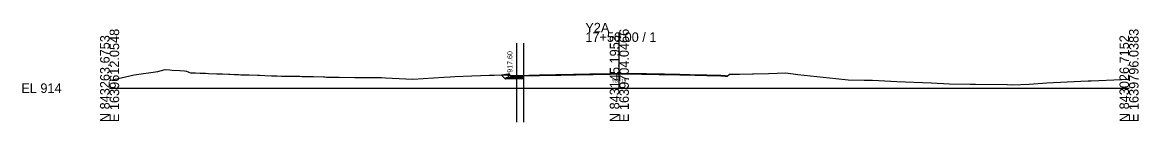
# Model space of a CAD drawing. Extents: x -26 to 303, y -10 to 10517.
# Drawn here: x -25.7 to 302.8, y 6989.9 to 7019.3 of the extents above; entities that cross this region are included whole.
import ezdxf

# ---------------------------------------------------------------- set-up
doc = ezdxf.new("R2010")
doc.units = 0
for name, color, linetype in [('Exist Cross Section Cell', 7, 'Continuous'), ('Exist XS Center Line Elevation Label', 7, 'Continuous'), ('Exist XS Ground Line', 7, 'Continuous'), ('Prop CMT Conc Surface', 7, 'Continuous'), ('Prop CMT Concrete Structures', 7, 'Continuous'), ('Prop CMT Pvmt Course 1', 7, 'Continuous'), ('Prop CMT Pvmt Course 1 CG', 7, 'Continuous'), ('Prop CMT Pvmt Course 2', 7, 'Continuous'), ('Prop CMT Pvmt Surface Overlay', 7, 'Continuous'), ('Prop CMT Slope Grass', 7, 'Continuous'), ('Prop CMT Subgrade Earthwork', 7, 'Continuous'), ('Prop XS Hydro Elevations', 7, 'Continuous'), ('Scratch_Level_0', 7, 'Continuous'), ('Scratch_Level_2', 7, 'Continuous')]:
    doc.layers.add(name, color=color, linetype=linetype)

msp = doc.modelspace()

# ---------------------------------------------------------------- linework, layer by layer
at = {"layer": 'Exist Cross Section Cell'}
for p, q in [((150, 7000), (150, 7016.43)), ((0, 7000), (150, 7000)), ((150, 7000), (300, 7000))]:
    msp.add_line(p, q, dxfattribs=at)
at = {"layer": 'Exist XS Ground Line'}
msp.add_lwpolyline([(0, 7002.24), (7.25, 7003.95), (14.19, 7004.92), (16.35, 7005.48), (17.74, 7005.39), (18.43, 7005.34), (20.7, 7005.16), (22.08, 7005.06), (22.61, 7005.02), (23.34, 7004.71), (23.76, 7004.53), (24.1, 7004.52), (25.23, 7004.51), (26.63, 7004.46), (27.63, 7004.41), (28.23, 7004.38), (29.07, 7004.34), (31.56, 7004.25), (33.23, 7004.18), (35.01, 7004.11), (35.38, 7004.1), (36.79, 7004.05), (37.89, 7004), (38.57, 7003.97), (39.45, 7003.94), (40.35, 7003.91), (41.05, 7003.89), (43.53, 7003.8), (44.22, 7003.78), (45.7, 7003.73), (47.61, 7003.67), (49.26, 7003.61), (50.55, 7003.55), (51.15, 7003.53), (52.55, 7003.53), (53.28, 7003.54), (53.75, 7003.53), (55.97, 7003.5), (56.53, 7003.48), (56.88, 7003.48), (58.17, 7003.44), (60.04, 7003.41), (62.94, 7003.31), (63.37, 7003.3), (63.8, 7003.28), (65.58, 7003.23), (67.53, 7003.19), (72.18, 7003.16), (74.02, 7003.13), (75.17, 7003.12), (75.67, 7003.11), (76.35, 7003.1), (80.01, 7003.09), (81.19, 7003.04), (87.18, 7002.74), (89.21, 7002.69), (98.34, 7003.28), (100.19, 7003.33), (101.57, 7003.39), (106.55, 7003.65), (111.66, 7003.81), (113.16, 7003.83), (117.53, 7003.89), (118.11, 7003.44), (118.57, 7003.46), (119.76, 7003.5), (120.25, 7003.57), (120.98, 7003.62), (123.34, 7003.68), (124.09, 7003.7), (125.06, 7003.72), (125.87, 7003.74), (126.51, 7003.76), (127.66, 7003.78), (129.13, 7003.82), (129.67, 7003.83), (131.36, 7003.86), (132.8, 7003.87), (133.21, 7003.88), (134.78, 7003.92), (136, 7003.94), (136.56, 7003.95), (137.29, 7003.97), (138.35, 7004), (139.17, 7004.01), (141.36, 7004.05), (142.33, 7004.07), (143.26, 7004.08), (145.5, 7004.11), (147.26, 7004.14), (148.66, 7004.17), (149.52, 7004.19), (150, 7004.19), (151.83, 7004.2), (152.6, 7004.2), (153.59, 7004.19), (154.99, 7004.18), (156.65, 7004.16), (157.41, 7004.15), (157.85, 7004.14), (158.16, 7004.14), (159.73, 7004.09), (161.75, 7004.07), (163.29, 7004.05), (164.49, 7004.01), (165.82, 7003.99), (167.78, 7003.96), (168.61, 7003.94), (169.84, 7003.91), (170.82, 7003.88), (172.2, 7003.84), (173.99, 7003.81), (175.76, 7003.75), (177.15, 7003.73), (177.54, 7003.72), (178.05, 7003.71), (179.84, 7003.66), (181.16, 7003.56), (181.78, 7003.52), (182.46, 7004.08), (182.96, 7004.09), (185.33, 7004.1), (189.18, 7004.2), (189.52, 7004.21), (193.9, 7004.33), (198.96, 7004.47), (202.52, 7004.07), (213.7, 7002.8), (217.37, 7002.49), (222.1, 7002.4), (224.5, 7002.37), (226.36, 7002.22), (231.62, 7001.99), (241.81, 7001.59), (247.21, 7001.32), (253.28, 7001.21), (254.11, 7001.19), (254.8, 7001.21), (264.25, 7001.04), (265.63, 7001.02), (270.66, 7001.19), (275.81, 7001.6), (285.83, 7002.04), (287.93, 7002.11), (288.89, 7002.14), (297.79, 7002.55), (300, 7002.65)], dxfattribs=at)
at = {"layer": 'Prop CMT Conc Surface'}
msp.add_lwpolyline([(117.78, 7003.6), (117.78, 7004.1), (117.28, 7004.1)], dxfattribs=at)
at = {"layer": 'Prop CMT Concrete Structures'}
for points in [[(119.78, 7003.72), (117.78, 7003.6), (117.78, 7004.1), (117.28, 7004.1)], [(117.28, 7004.1), (117.28, 7003.09), (119.78, 7003.14)]]:
    msp.add_lwpolyline(points, dxfattribs=at)
at = {"layer": 'Prop CMT Pvmt Course 1'}
for p, q in [((119.78, 7003.72), (121.78, 7003.76)), ((119.78, 7003.72), (119.78, 7003.47)), ((119.78, 7003.47), (121.78, 7003.51)), ((121.78, 7003.76), (121.78, 7003.51))]:
    msp.add_line(p, q, dxfattribs=at)
at = {"layer": 'Prop CMT Pvmt Course 1 CG'}
for p, q in [((119.78, 7003.14), (119.78, 7002.81)), ((119.78, 7002.81), (121.78, 7002.85)), ((121.78, 7003.18), (121.78, 7002.85))]:
    msp.add_line(p, q, dxfattribs=at)
for points in [[(119.78, 7003.14), (116.78, 7003.08), (116.44, 7002.74)], [(116.48, 7002.75), (119.78, 7002.81)]]:
    msp.add_lwpolyline(points, dxfattribs=at)
at = {"layer": 'Prop CMT Pvmt Course 2'}
for p, q in [((119.78, 7003.14), (119.78, 7003.47)), ((119.78, 7003.14), (121.78, 7003.18)), ((121.78, 7003.18), (121.78, 7003.51))]:
    msp.add_line(p, q, dxfattribs=at)
at = {"layer": 'Prop CMT Pvmt Surface Overlay'}
msp.add_lwpolyline([(121.78, 7003.76), (123.34, 7003.8), (124.09, 7003.82), (125.05, 7003.85), (126.51, 7003.88), (127.65, 7003.9), (129.13, 7003.94), (129.67, 7003.95), (131.36, 7003.98), (132.8, 7004), (133.21, 7004.01), (134.78, 7004.05), (136, 7004.06), (136.56, 7004.08), (137.28, 7004.1), (138.34, 7004.12), (139.17, 7004.14), (141.36, 7004.17), (142.33, 7004.2), (143.25, 7004.21), (145.5, 7004.23), (147.25, 7004.27), (148.66, 7004.3), (149.51, 7004.31), (151.83, 7004.33), (152.6, 7004.33), (153.59, 7004.32), (155, 7004.31), (156.65, 7004.29), (157.41, 7004.27), (157.85, 7004.27), (158.16, 7004.26), (159.73, 7004.22), (161.75, 7004.2), (163.29, 7004.17), (164.49, 7004.13), (165.82, 7004.11), (167.79, 7004.09), (168.61, 7004.06), (169.84, 7004.03), (170.82, 7004), (172.2, 7003.97), (173.99, 7003.94), (175.77, 7003.88), (177.15, 7003.85), (177.55, 7003.85), (178.05, 7003.84), (179.84, 7003.78), (181.17, 7003.69), (181.92, 7003.63)], dxfattribs=at)
at = {"layer": 'Prop CMT Slope Grass'}
msp.add_lwpolyline([(117.28, 7004.1), (115.33, 7003.86)], dxfattribs=at)
at = {"layer": 'Prop CMT Subgrade Earthwork'}
msp.add_lwpolyline([(119.78, 7002.81), (116.44, 7002.74), (115.33, 7003.86)], dxfattribs=at)
at = {"layer": 'Scratch_Level_0'}
for p, q in [((119.78, 7013.29), (119.78, 6989.94)), ((121.78, 7013.29), (121.78, 6989.94))]:
    msp.add_line(p, q, dxfattribs=at)
at = {"layer": 'Scratch_Level_2'}
msp.add_line((121.78, 7003.64), (120.98, 7003.62), dxfattribs=at)
for points in [[(120.98, 7003.62), (120.25, 7003.57), (119.76, 7003.5), (118.57, 7003.46), (118.11, 7003.44), (117.53, 7003.89), (115.33, 7003.86)], [(115.33, 7003.86), (116.44, 7002.74), (119.78, 7002.81), (121.78, 7002.85), (121.78, 7003.64)], [(115.33, 7003.86), (116.44, 7002.74), (119.78, 7002.81), (121.78, 7002.85), (121.78, 7003.64)]]:
    msp.add_lwpolyline(points, dxfattribs=at)

# ---------------------------------------------------------------- texts
at = {"layer": 'Exist Cross Section Cell'}
for s, p in [('Y2A', (140, 7016.43)), ('17+50.00 / 1', (140, 7013.63)), ('EL 914', (-26, 6998.6))]:
    msp.add_text(s, height=2.8, dxfattribs=at).set_placement(p)
for s, p in [('N 843263.6753', (0, 6990)), ('E 1639612.0548', (2.8, 6990)), ('N 843145.1953', (150, 6990)), ('E 1639704.0466', (152.8, 6990)), ('N 843026.7152', (300, 6990)), ('E 1639796.0383', (302.8, 6990))]:
    msp.add_text(s, height=2.8, rotation=90, dxfattribs=at).set_placement(p)
at = {"layer": 'Exist XS Center Line Elevation Label'}
msp.add_text('918.19', height=1, dxfattribs=at).set_placement((147.83, 7001.74))
at = {"layer": 'Prop XS Hydro Elevations'}
msp.add_text('917.60', height=1.5, rotation=90, dxfattribs=at).set_placement((118.53, 7004.56))

doc.saveas('drawing.dxf')
